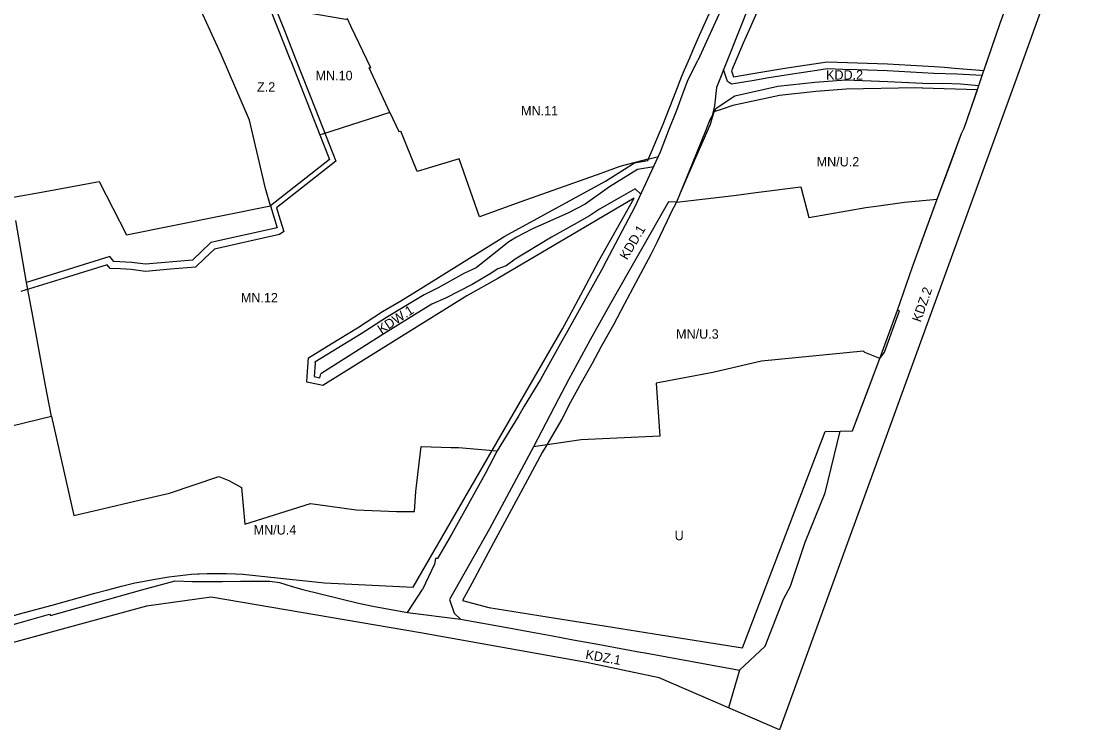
# Model space of a CAD drawing. Extents: x 7422113 to 7423305, y 5541775 to 5542397.
# Drawn here: x 7422622.5 to 7423071.4, y 5541775.3 to 5542077 of the extents above; entities that cross this region are included whole.
import ezdxf

# ---------------------------------------------------------------- set-up
doc = ezdxf.new("R2010")
doc.units = 0
for name, color, linetype in [('GRANICA OBSZARU OBJĘTEGO PLANEM', 7, 'Continuous'), ('LINIE ROZGRANICZAJĄCE TERENY O RÓZNYM PRZEZNACZENIU LUB RÓZNYCH ZASADACH ZAGOSPODAROWANIA', 7, 'Continuous'), ('NIEPRZEKRACZALNE LINIE ZABUDOWY', 7, 'Continuous'), ('OZNACZENIA TERENÓW', 7, 'Continuous')]:
    doc.layers.add(name, color=color, linetype=linetype)

msp = doc.modelspace()

# ---------------------------------------------------------------- linework, layer by layer
at = {"layer": 'GRANICA OBSZARU OBJĘTEGO PLANEM'}
for p, q in [((7422719.69, 5542034.86), (7422707.75, 5542062.74)), ((7422726.58, 5542005.72), (7422719.69, 5542034.86)), ((7422728.66, 5541998.32), (7422726.58, 5542005.72)), ((7422953.24, 5541797.15), (7422945.3, 5541775.27))]:
    msp.add_line(p, q, dxfattribs=at)
for points in [[(7423083.61, 5542157), (7423045.92, 5542052.34), (7422953.24, 5541797.15)], [(7422707.75, 5542062.74), (7422699.91, 5542079.88), (7422698.88, 5542107.06)], [(7422590.99, 5541998.45), (7422618.44, 5542001.87), (7422632.81, 5542004.51), (7422648.05, 5542007.32), (7422655.74, 5542008.74), (7422667.39, 5541985.98), (7422728.66, 5541998.32)], [(7422945.3, 5541775.27), (7422894.05, 5541797.48), (7422863.17, 5541803.92), (7422792.47, 5541816.58), (7422703.41, 5541831.78), (7422675.92, 5541827.96), (7422589, 5541804.3)]]:
    msp.add_lwpolyline(points, dxfattribs=at)
at = {"layer": 'LINIE ROZGRANICZAJĄCE TERENY O RÓZNYM PRZEZNACZENIU LUB RÓZNYCH ZASADACH ZAGOSPODAROWANIA'}
for p, q in [((7422719.69, 5542034.86), (7422707.75, 5542062.74)), ((7422771.3, 5542057.07), (7422770.65, 5542057.12)), ((7422726.58, 5542005.72), (7422719.69, 5542034.86)), ((7422883.85, 5541998.07), (7422894.64, 5542021.42)), ((7422728.66, 5541998.32), (7422726.58, 5542005.72)), ((7422870.2, 5541972.3), (7422883.85, 5541998.07)), ((7422635.42, 5541908.64), (7422632.96, 5541921.94)), ((7422787.03, 5541825.24), (7422809.49, 5541822.46)), ((7422928.18, 5541800.73), (7422923.59, 5541784.62)), ((7422953.24, 5541797.15), (7422945.3, 5541775.27))]:
    msp.add_line(p, q, dxfattribs=at)
for points in [[(7423083.61, 5542157), (7423045.92, 5542052.34), (7422953.24, 5541797.15)], [(7423012.42, 5542001.17), (7423022.72, 5542029.19), (7423023.87, 5542031.46), (7423030.11, 5542049.62), (7423031.56, 5542053.88), (7423037.05, 5542069.88), (7423039.21, 5542076.18), (7423041.14, 5542081.47), (7423044.48, 5542090.62), (7423052.51, 5542112.62), (7423054.71, 5542118.66), (7423060.39, 5542134.23), (7423069.36, 5542157.71), (7423069.36, 5542157.71), (7423069.36, 5542157.71)], [(7422949.56, 5542120.04), (7422932.54, 5542084.08), (7422918.43, 5542048.75), (7422917.6, 5542040.9), (7422916.57, 5542036.66)], [(7422707.75, 5542062.74), (7422699.91, 5542079.88), (7422698.88, 5542107.06)], [(7422922.39, 5542086.44), (7422910.48, 5542060.24), (7422910.48, 5542060.24), (7422910.48, 5542060.24), (7422910.48, 5542060.24)], [(7422737.3, 5542060.1), (7422728.69, 5542081.94), (7422728.69, 5542081.94), (7422728.69, 5542081.94)], [(7422763.01, 5542074.63), (7422761.46, 5542077.92), (7422760.7, 5542077.72), (7422743.28, 5542080.63)], [(7422771.3, 5542057.07), (7422771.3, 5542057.07), (7422771.3, 5542057.07), (7422763.01, 5542074.63)], [(7422737.3, 5542060.1), (7422753.81, 5542018.12), (7422728.66, 5541998.32), (7422731.55, 5541989.04), (7422703.31, 5541982.7), (7422695.5, 5541975.21), (7422675.5, 5541973.47), (7422669.66, 5541974.25), (7422661.94, 5541974.68), (7422660.37, 5541976.77), (7422624.83, 5541965.77), (7422620.26, 5541992.07)], [(7422779.46, 5542038.15), (7422770.65, 5542057.12)], [(7422894.64, 5542021.42), (7422898.08, 5542030.25), (7422901.51, 5542039.08), (7422903.82, 5542045.28), (7422906.13, 5542051.48), (7422908.31, 5542055.86), (7422910.48, 5542060.24)], [(7423031.55, 5542053.85), (7423020.77, 5542054.4), (7423010.97, 5542054.75), (7422991.09, 5542055.84), (7422978.41, 5542056.26), (7422972.15, 5542056.47), (7422965.72, 5542056.68), (7422962.96, 5542056.28), (7422947.93, 5542054), (7422939.81, 5542052.73), (7422934.47, 5542051.78), (7422924.79, 5542050.12), (7422923.16, 5542051.29), (7422921.49, 5542056.41)], [(7422916.57, 5542036.66), (7422918.34, 5542039.91), (7422926.25, 5542045.22), (7422944.59, 5542049.26), (7422960.36, 5542050.99), (7422973.54, 5542051.98), (7422991.33, 5542051.23), (7423009.19, 5542050.49), (7423014.72, 5542050.58), (7423022.23, 5542050.25), (7423030.11, 5542049.62)], [(7422779.46, 5542038.15), (7422750.83, 5542028.92), (7422749.71, 5542028.56)], [(7422779.46, 5542038.15), (7422783.22, 5542030.06), (7422784.11, 5542030.19)], [(7422916.57, 5542036.66), (7422915.66, 5542034.99), (7422913.91, 5542030.64), (7422908.4, 5542017.01), (7422901.41, 5541999.92)], [(7422869.17, 5542012.15), (7422835.24, 5542000.02), (7422817.6, 5541993.68), (7422809.01, 5542018.35), (7422791.13, 5542012.97), (7422784.11, 5542030.19)], [(7422889.78, 5542018.39), (7422877.27, 5542015.07), (7422869.17, 5542012.15)], [(7422889.78, 5542018.39), (7422893.72, 5542019.44)], [(7422891.74, 5542014.96), (7422884.79, 5542013.82), (7422872.95, 5542006.41), (7422862.61, 5541999.1), (7422855.44, 5541995.33), (7422839.91, 5541988.44), (7422833.41, 5541985.03), (7422830.05, 5541983.02), (7422816.22, 5541972.02), (7422811.27, 5541969.77), (7422799.99, 5541963.46), (7422794.08, 5541960.53), (7422785.62, 5541955.37), (7422777.98, 5541950.83), (7422767.27, 5541943.9), (7422747.53, 5541931.87)], [(7422590.99, 5541998.45), (7422618.44, 5542001.87), (7422632.81, 5542004.51), (7422648.05, 5542007.32), (7422655.74, 5542008.74), (7422667.39, 5541985.98), (7422728.66, 5541998.32)], [(7422883.84, 5542005.67), (7422877.83, 5542002.24), (7422868.7, 5541996.95), (7422864.45, 5541994.05), (7422857.92, 5541990.46), (7422848.27, 5541985.03), (7422832.85, 5541975.68), (7422828.94, 5541972.88), (7422825.44, 5541971.59), (7422822.19, 5541969.38), (7422814.46, 5541964.86), (7422803.11, 5541959.04), (7422797.37, 5541956.55), (7422792.96, 5541953.83), (7422776.87, 5541943.81), (7422750.1, 5541926.84)], [(7422886.27, 5542003.31), (7422883.84, 5542005.67)], [(7422901.41, 5541999.92), (7422925.86, 5542002.83), (7422935.23, 5542004.07), (7422954.33, 5542006.5), (7422957.75, 5541993.39), (7422981.96, 5541997.64), (7422986.34, 5541998.26), (7422998.45, 5541999.98), (7423012.42, 5542001.17)], [(7422901.41, 5541999.92), (7422898.04, 5542000.02), (7422873.39, 5541956.82), (7422864.72, 5541941.31), (7422855.45, 5541924.26), (7422851.24, 5541916.25), (7422840.53, 5541895.79), (7422821.85, 5541860.88), (7422804.86, 5541830.79), (7422806.87, 5541825.02), (7422809.48, 5541822.48)], [(7422995.46, 5541953.94), (7423001.87, 5541972.45), (7423012.42, 5542001.15)], [(7422870.2, 5541972.3), (7422870.2, 5541972.3), (7422870.2, 5541972.3), (7422854.45, 5541944.06), (7422852.77, 5541940.98), (7422843.6, 5541924.46), (7422836.68, 5541913.04), (7422834.34, 5541909.17), (7422825.18, 5541894.08), (7422820.08, 5541884.29), (7422805.74, 5541858.47), (7422799.73, 5541848.24), (7422798.88, 5541848.3), (7422798.46, 5541845.77), (7422793.34, 5541835.06)], [(7422632.96, 5541921.94), (7422627.25, 5541952.98), (7422624.83, 5541965.77)], [(7422987.93, 5541933.36), (7422989.93, 5541936.06), (7422996.31, 5541953.65), (7422995.45, 5541953.96)], [(7422987.93, 5541933.36), (7422981.52, 5541935.96), (7422980.96, 5541936.48), (7422937.65, 5541932.24), (7422916.88, 5541927.46), (7422892.81, 5541922.92), (7422894.41, 5541900.28), (7422860.89, 5541898.77), (7422840.53, 5541895.79)], [(7422747.53, 5541931.87), (7422747.65, 5541931.46), (7422747.27, 5541925.71)], [(7422809.49, 5541822.46), (7422830.07, 5541818.69), (7422839.3, 5541816.99), (7422848.61, 5541815.29), (7422857.47, 5541813.66), (7422867.9, 5541811.74), (7422879.96, 5541809.54), (7422886.1, 5541808.42), (7422888.15, 5541808.05), (7422897.28, 5541806.38), (7422926.03, 5541801.12), (7422928.19, 5541800.71), (7422939.12, 5541810.97), (7422946.93, 5541830.91), (7422949.96, 5541836.53), (7422956.17, 5541855.15), (7422964.73, 5541876.24), (7422971.13, 5541902.47), (7422976.34, 5541902.59), (7422987.94, 5541933.34)], [(7422747.27, 5541925.71), (7422749.66, 5541925.19), (7422750.1, 5541926.84)], [(7422635.45, 5541908.64), (7422601.02, 5541900.25), (7422601.92, 5541896.79)], [(7422635.45, 5541908.64), (7422645.02, 5541866.61), (7422657.78, 5541869.57), (7422670.94, 5541872.62), (7422685.69, 5541876.04), (7422706.72, 5541883.1), (7422710.89, 5541881.41), (7422716.31, 5541878.48), (7422717.73, 5541862.82), (7422745.71, 5541871.65), (7422748.79, 5541871.2), (7422765.16, 5541868.98), (7422782.26, 5541868.29), (7422789.98, 5541868.31), (7422790.55, 5541876.77), (7422792.82, 5541895.93), (7422805.5, 5541895.56), (7422808.69, 5541895.47), (7422825.18, 5541894.08)], [(7422673.89, 5541834.93), (7422688.08, 5541838.7), (7422695.35, 5541838.48), (7422708.23, 5541838.52), (7422715.87, 5541838.54), (7422728.32, 5541838.59), (7422732.52, 5541838.06), (7422737.93, 5541836.39), (7422742.43, 5541835.08), (7422766.13, 5541829.26)], [(7422634.61, 5541824.57), (7422635.09, 5541823.91), (7422654.73, 5541829.44), (7422673.89, 5541834.93)], [(7422766.13, 5541829.26), (7422772.18, 5541827.91), (7422787.03, 5541825.24), (7422793.34, 5541835.06)], [(7422945.3, 5541775.27), (7422894.05, 5541797.48), (7422863.17, 5541803.92), (7422792.47, 5541816.58), (7422703.41, 5541831.78), (7422675.92, 5541827.96), (7422589, 5541804.3)], [(7422441.82, 5541817.09), (7422446.89, 5541814.68), (7422449.47, 5541813.9), (7422452.03, 5541812.67), (7422461.18, 5541808.65), (7422466.42, 5541806.24), (7422471.86, 5541805.01), (7422484.38, 5541803.92), (7422499.7, 5541802.48), (7422505.75, 5541802.19), (7422521.41, 5541801.13), (7422536.06, 5541800.8), (7422538.02, 5541800.91), (7422546, 5541800.94), (7422556.87, 5541803.84), (7422566.12, 5541806.04), (7422583.71, 5541810.08), (7422585.31, 5541810.44), (7422591.45, 5541812.42), (7422605.34, 5541816.63), (7422613.43, 5541818.62), (7422621.75, 5541820.84), (7422634.61, 5541824.57)]]:
    msp.add_lwpolyline(points, dxfattribs=at)
at = {"layer": 'NIEPRZEKRACZALNE LINIE ZABUDOWY'}
for p, q in [((7422729.84, 5542084.9), (7422733.08, 5542076.88)), ((7422883.36, 5542001.63), (7422825.42, 5541967.42)), ((7422943.84, 5541847.7), (7422964.69, 5541902.35)), ((7422789.33, 5541836), (7422822.95, 5541894.22))]:
    msp.add_line(p, q, dxfattribs=at)
for points in [[(7422971.56, 5542161.09), (7422971.56, 5542161.09), (7422958.98, 5542133.87), (7422958.98, 5542133.87), (7422954.41, 5542123.63), (7422932.29, 5542073.23), (7422932.29, 5542073.23), (7422932.29, 5542073.23), (7422932.29, 5542073.23)], [(7423032.22, 5542055.79), (7423039.21, 5542076.18), (7423048.49, 5542101.62), (7423053.61, 5542115.64), (7423057.55, 5542126.45), (7423060.39, 5542134.23), (7423064.88, 5542145.97), (7423069.36, 5542157.71)], [(7422911.21, 5542070.96), (7422918.07, 5542086.27)], [(7422733.08, 5542076.88), (7422733.08, 5542076.88), (7422733.08, 5542076.88), (7422733.08, 5542076.88), (7422733.08, 5542076.88), (7422733.08, 5542076.88), (7422733.08, 5542076.88), (7422734.57, 5542073.01), (7422739.35, 5542060.91), (7422747.9, 5542039.16), (7422756.46, 5542017.4), (7422743.83, 5542007.47), (7422731.21, 5541997.53), (7422732.79, 5541992.47), (7422734.36, 5541987.42), (7422732.53, 5541986.19), (7422718.66, 5541983.07), (7422704.78, 5541979.95), (7422700.8, 5541976.13), (7422696.81, 5541972.31), (7422686.12, 5541971.38), (7422675.43, 5541970.46), (7422669.38, 5541971.26), (7422664.88, 5541971.51), (7422660.38, 5541971.76), (7422659.24, 5541973.28), (7422640.85, 5541967.59), (7422622.46, 5541961.9)], [(7422889.23, 5542017.61), (7422895.75, 5542033.07), (7422901.18, 5542046.96), (7422903.77, 5542053.57), (7422904.79, 5542056.24), (7422907.05, 5542061.37), (7422908.37, 5542064.55), (7422911.21, 5542070.96)], [(7422932.29, 5542073.23), (7422929.83, 5542067.56), (7422924.79, 5542055.9), (7422925.66, 5542053.31), (7422933.95, 5542054.73), (7422947.47, 5542056.97), (7422965.55, 5542059.69), (7422978.39, 5542059.26), (7422991.22, 5542058.84), (7423001.16, 5542058.29), (7423011.11, 5542057.75), (7423015.42, 5542057.35), (7423019.73, 5542056.95), (7423032.29, 5542056)], [(7423006.26, 5542048.49), (7423003.33, 5542048.59), (7422973.61, 5542047.97), (7422960.73, 5542047.01), (7422945.24, 5542045.31), (7422925.42, 5542041.08)], [(7423026.38, 5542038.79), (7423029.52, 5542047.77), (7423005.92, 5542048.51)], [(7422925.42, 5542041.08), (7422921.35, 5542039.73), (7422917.28, 5542038.38), (7422915.69, 5542033.01), (7422907.98, 5542015.23), (7422903.43, 5542004.73), (7422901.25, 5541999.69), (7422899.18, 5541995.64), (7422897.47, 5541992.05), (7422895.76, 5541988.46), (7422893.17, 5541983.08), (7422890.57, 5541977.71), (7422887.31, 5541971.59), (7422884.05, 5541965.47), (7422884.05, 5541965.47), (7422879.33, 5541956.59), (7422874.6, 5541947.72), (7422869.4, 5541938.54), (7422865.49, 5541931.29), (7422860.92, 5541923.03), (7422856.36, 5541914.77), (7422852.68, 5541907.53), (7422848.25, 5541900.04), (7422846.22, 5541896.62)], [(7422987.93, 5541933.36), (7422995.45, 5541953.96), (7423001.86, 5541972.47), (7423007.14, 5541986.82), (7423012.42, 5542001.17), (7423017.57, 5542015.18), (7423022.72, 5542029.19), (7423023.87, 5542031.46), (7423026.38, 5542038.79), (7423026.38, 5542038.79), (7423026.38, 5542038.79)], [(7422744.79, 5541933.73), (7422754.48, 5541939.62), (7422765.68, 5541946.44), (7422776.4, 5541953.38), (7422784.08, 5541957.94), (7422792.63, 5541963.15), (7422828.34, 5541985.49), (7422871.24, 5542008.88), (7422883.52, 5542016.73), (7422889.23, 5542017.61)], [(7422822.95, 5541894.22), (7422852.87, 5541946.07), (7422857.45, 5541954.36), (7422863.06, 5541964.75), (7422868.33, 5541974.9), (7422883.36, 5542001.63)], [(7422825.42, 5541967.42), (7422812.26, 5541960.08), (7422750.99, 5541921.83)], [(7422744.1, 5541923.33), (7422744.28, 5541925.91), (7422744.79, 5541933.73)], [(7422976.34, 5541902.59), (7422982.14, 5541917.96), (7422987.93, 5541933.36)], [(7422750.99, 5541921.83), (7422749.02, 5541922.26), (7422744.1, 5541923.33)], [(7422964.69, 5541902.35), (7422971.13, 5541902.47), (7422976.34, 5541902.59)], [(7422846.22, 5541896.62), (7422844.3, 5541893.34), (7422837.99, 5541881.71), (7422830.19, 5541867.22), (7422823.62, 5541854.95), (7422819.01, 5541846.33), (7422814.29, 5541837.62)], [(7422891.97, 5541816.23), (7422929.55, 5541810.26), (7422943.84, 5541847.7)], [(7422672.65, 5541838.19), (7422678.77, 5541839.37), (7422685.39, 5541840.49), (7422694.99, 5541841.55), (7422697.77, 5541841.68)], [(7422697.77, 5541841.68), (7422698.35, 5541841.71), (7422701.71, 5541841.87), (7422706.09, 5541841.92), (7422709.91, 5541841.82), (7422713.74, 5541841.71), (7422716.85, 5541841.55)], [(7422607.38, 5541820.68), (7422613.78, 5541822.43), (7422619.07, 5541823.82), (7422621.88, 5541824.68), (7422635.71, 5541828.4), (7422648.45, 5541831.91), (7422653.99, 5541833.43), (7422659.52, 5541834.95), (7422665.21, 5541836.4), (7422670.9, 5541837.84), (7422672.65, 5541838.19)], [(7422716.89, 5541841.55), (7422734.24, 5541839.71), (7422751.59, 5541837.87), (7422789.33, 5541836)], [(7422814.29, 5541837.62), (7422810.33, 5541830.33), (7422821.64, 5541827.39), (7422849.99, 5541822.89), (7422870.63, 5541819.61), (7422891.97, 5541816.23)]]:
    msp.add_lwpolyline(points, dxfattribs=at)

# ---------------------------------------------------------------- texts
at = {"layer": 'OZNACZENIA TERENÓW'}
for s, p in [('MN.10', (7422747.85, 5542051.84)), ('KDD.2', (7422965.08, 5542052.11)), ('Z.2', (7422722.96, 5542046.99)), ('MN.11', (7422835.3, 5542036.83)), ('MN/U.2', (7422961.07, 5542015.15)), ('MN.12', (7422716.07, 5541957.27)), ('MN/U.3', (7422901.25, 5541941.82)), ('MN/U.4', (7422721.51, 5541858.44)), ('U', (7422900.65, 5541856.02))]:
    msp.add_text(s, height=4, dxfattribs=at).set_placement(p)
for s, rotation, p in [('KDD.1', 59.207, (7422880.4, 5541975.06)), ('KDZ.2', 70.7814, (7423005.33, 5541948.58)), ('KDW.1', 33.1956, (7422775.86, 5541943.69)), ('KDZ.1', 349.8937, (7422862.49, 5541805.55))]:
    msp.add_text(s, height=4, rotation=rotation, dxfattribs=at).set_placement(p)

doc.saveas('drawing.dxf')
